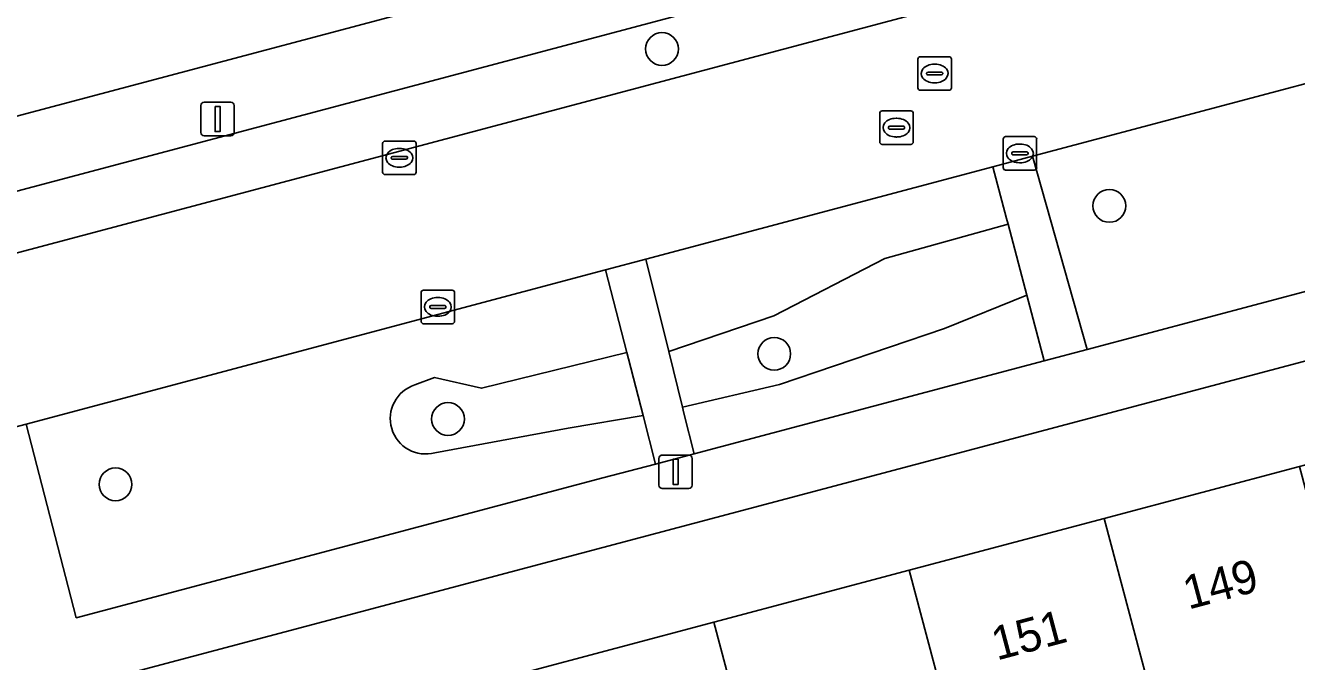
# Model space of a CAD drawing. Extents: x 162542 to 163147, y 380779 to 381521.
# Drawn here: x 162694.02 to 162731.96, y 381102.27 to 381121.27 of the extents above; entities that cross this region are included whole.
import ezdxf

# ---------------------------------------------------------------- set-up
doc = ezdxf.new("R2010")
doc.units = 0
for name, color, linetype in [('IMGEO_Boom', 7, 'Continuous'), ('IMGEO_Erf', 7, 'Continuous'), ('IMGEO_Groenvoorziening', 7, 'Continuous'), ('IMGEO_Kolk', 7, 'Continuous'), ('IMGEO_Lichtmast', 7, 'Continuous'), ('IMGEO_Pand', 7, 'Continuous'), ('IMGEO_Pand_nummerreeks', 7, 'Continuous'), ('IMGEO_Parkeervlak_open', 7, 'Continuous'), ('IMGEO_Rijbaan_lokaal_open', 7, 'Continuous'), ('IMGEO_Rioolput', 7, 'Continuous'), ('IMGEO_Voetpad_open', 7, 'Continuous')]:
    doc.layers.add(name, color=color, linetype=linetype)

msp = doc.modelspace()

# ---------------------------------------------------------------- linework, layer by layer
at = {"layer": 'IMGEO_Boom'}
for centre in [(162713.018, 381120.562), (162726.37, 381115.877), (162716.369, 381111.459), (162706.631, 381109.515), (162696.71, 381107.565)]:
    msp.add_circle(centre, 0.489, dxfattribs=at)
at = {"layer": 'IMGEO_Erf'}
for points in [[(162749.869, 381133.472), (162749.085, 381136.384), (162743.131, 381134.8), (162737.328, 381133.255), (162731.525, 381131.711), (162725.722, 381130.167), (162719.919, 381128.623), (162714.116, 381127.079), (162708.313, 381125.534), (162702.51, 381123.99), (162696.707, 381122.446), (162690.904, 381120.902), (162684.977, 381119.324), (162684.888, 381119.301), (162684.115, 381122.206), (162678.746, 381120.787), (162680.279, 381114.986), (162685.734, 381116.428)], [(162732.042, 381108.097), (162737.868, 381109.646), (162743.693, 381111.195), (162749.519, 381112.744), (162755.344, 381114.293), (162761.17, 381115.842), (162761.884, 381112.936), (162767.441, 381114.419), (162765.901, 381120.189), (162760.455, 381118.748), (162696.302, 381101.71), (162697.083, 381098.802), (162702.914, 381100.353), (162708.739, 381101.902), (162714.565, 381103.451), (162720.391, 381104.999), (162726.216, 381106.548)]]:
    msp.add_lwpolyline(points, close=True, dxfattribs=at)
at = {"layer": 'IMGEO_Groenvoorziening'}
for points in [[(162724.071, 381117.358), (162725.703, 381111.591), (162736.038, 381114.335), (162734.561, 381120.153)], [(162723.348, 381115.329), (162723.302, 381115.505), (162722.896, 381117.045), (162712.54, 381114.286), (162713.22, 381111.534), (162716.356, 381112.599), (162719.667, 381114.311)], [(162723.906, 381113.217), (162723.348, 381115.329), (162719.667, 381114.311), (162716.356, 381112.599), (162713.22, 381111.534), (162713.631, 381109.869), (162716.529, 381110.546), (162721.454, 381112.219)], [(162722.471, 381110.733), (162724.424, 381111.251), (162723.906, 381113.217), (162721.454, 381112.219), (162716.529, 381110.546), (162713.631, 381109.869), (162713.674, 381109.694), (162713.974, 381108.477)]]:
    msp.add_lwpolyline(points, close=True, dxfattribs=at)
for points in [[(162711.97, 381111.5), (162711.337, 381113.966), (162694.038, 381109.357), (162695.539, 381103.583), (162711.256, 381107.755), (162712.824, 381108.171), (162712.452, 381109.619), (162710.222, 381109.238), (162706.243, 381108.509)], [(162705.645, 381110.534), (162706.226, 381110.759), (162707.629, 381110.434), (162711.97, 381111.5)], [(162712.018, 381111.312), (162711.97, 381111.5), (162707.629, 381110.434), (162706.226, 381110.759), (162705.645, 381110.534)], [(162706.243, 381108.509), (162710.222, 381109.238), (162712.452, 381109.619), (162712.018, 381111.312)]]:
    msp.add_lwpolyline(points, dxfattribs=at)
msp.add_arc((162705.964, 381109.527), 1.056, 107.5972, 285.3075, dxfattribs=at)
msp.add_arc((162705.964, 381109.527), 1.056, 107.5972, 285.3075, dxfattribs=at)
at = {"layer": 'IMGEO_Kolk'}
for p, q in [((162723.274, 381117.945), (162724.126, 381117.945)), ((162704.679, 381116.887), (162704.679, 381117.739)), ((162704.754, 381117.813), (162705.606, 381117.813)), ((162705.167, 381117.593), (162705.192, 381117.593)), ((162705.68, 381117.739), (162705.68, 381116.887)), ((162723.199, 381117.019), (162723.199, 381117.871)), ((162723.687, 381117.725), (162723.712, 381117.725)), ((162724.2, 381117.871), (162724.2, 381117.019)), ((162704.938, 381117.307), (162704.938, 381117.319)), ((162705.376, 381117.27), (162704.978, 381117.27)), ((162704.981, 381117.356), (162705.379, 381117.356)), ((162705.422, 381117.319), (162705.422, 381117.307)), ((162723.458, 381117.439), (162723.458, 381117.451)), ((162723.896, 381117.402), (162723.498, 381117.402)), ((162723.501, 381117.488), (162723.899, 381117.488)), ((162723.71, 381117.165), (162723.685, 381117.165)), ((162723.942, 381117.451), (162723.942, 381117.439)), ((162705.606, 381116.813), (162704.754, 381116.813)), ((162705.19, 381117.033), (162705.165, 381117.033)), ((162724.126, 381116.945), (162723.274, 381116.945)), ((162705.827, 381112.435), (162705.827, 381113.287)), ((162705.902, 381113.361), (162706.754, 381113.361)), ((162706.315, 381113.141), (162706.34, 381113.141)), ((162706.828, 381113.287), (162706.828, 381112.435)), ((162706.086, 381112.855), (162706.086, 381112.867)), ((162706.524, 381112.818), (162706.126, 381112.818)), ((162706.129, 381112.904), (162706.527, 381112.904)), ((162706.57, 381112.867), (162706.57, 381112.855)), ((162706.754, 381112.361), (162705.902, 381112.361)), ((162706.338, 381112.581), (162706.313, 381112.581))]:
    msp.add_line(p, q, dxfattribs=at)
for points in [[(162723.274, 381117.945), (162724.126, 381117.945)], [(162704.679, 381116.887), (162704.679, 381117.739)], [(162704.754, 381117.813), (162705.606, 381117.813)], [(162705.68, 381117.739), (162705.68, 381116.887)], [(162723.199, 381117.019), (162723.199, 381117.871)], [(162724.2, 381117.871), (162724.2, 381117.019)], [(162705.606, 381116.813), (162704.754, 381116.813)], [(162724.126, 381116.945), (162723.274, 381116.945)], [(162705.827, 381112.435), (162705.827, 381113.287)], [(162705.902, 381113.361), (162706.754, 381113.361)], [(162706.828, 381113.287), (162706.828, 381112.435)], [(162706.754, 381112.361), (162705.902, 381112.361)]]:
    msp.add_lwpolyline(points, dxfattribs=at)
for centre, radius, start, end in [((162723.276, 381117.869), 0.0765, 91.552, 178.448), ((162723.276, 381117.869), 0.0765, 91.552, 178.448), ((162724.124, 381117.869), 0.0765, 1.552, 88.448), ((162724.124, 381117.869), 0.0765, 1.552, 88.448), ((162704.756, 381117.737), 0.0765, 91.552, 178.448), ((162704.756, 381117.737), 0.0765, 91.552, 178.448), ((162705.604, 381117.737), 0.0765, 1.552, 88.448), ((162705.604, 381117.737), 0.0765, 1.552, 88.448), ((162704.978, 381117.316), 0.0403, 85.8775, 175.7526), ((162704.975, 381117.306), 0.0366, 178.938, 274.7102), ((162705.379, 381117.313), 0.043, 264.8664, 352.4533), ((162705.383, 381117.318), 0.0386, 1.7309, 96.639), ((162723.498, 381117.448), 0.0403, 85.8775, 175.7526), ((162723.495, 381117.438), 0.0366, 178.938, 274.7102), ((162723.899, 381117.445), 0.043, 264.8664, 352.4533), ((162723.903, 381117.45), 0.0386, 1.7309, 96.639), ((162704.756, 381116.889), 0.0765, 181.552, 268.448), ((162704.756, 381116.889), 0.0765, 181.552, 268.448), ((162705.604, 381116.889), 0.0765, 271.552, 358.448), ((162705.604, 381116.889), 0.0765, 271.552, 358.448), ((162723.276, 381117.021), 0.0765, 181.552, 268.448), ((162723.276, 381117.021), 0.0765, 181.552, 268.448), ((162724.124, 381117.021), 0.0765, 271.552, 358.448), ((162724.124, 381117.021), 0.0765, 271.552, 358.448), ((162705.904, 381113.285), 0.0765, 91.552, 178.448), ((162705.904, 381113.285), 0.0765, 91.552, 178.448), ((162706.752, 381113.285), 0.0765, 1.552, 88.448), ((162706.752, 381113.285), 0.0765, 1.552, 88.448), ((162706.126, 381112.864), 0.0403, 85.8775, 175.7526), ((162706.123, 381112.854), 0.0366, 178.938, 274.7102), ((162706.527, 381112.861), 0.043, 264.8664, 352.4533), ((162706.531, 381112.866), 0.0386, 1.7309, 96.639), ((162705.904, 381112.437), 0.0765, 181.552, 268.448), ((162705.904, 381112.437), 0.0765, 181.552, 268.448), ((162706.752, 381112.437), 0.0765, 271.552, 358.448), ((162706.752, 381112.437), 0.0765, 271.552, 358.448)]:
    msp.add_arc(centre, radius, start, end, dxfattribs=at)
for centre, major_axis, ratio, start_param, end_param in [((162705.166, 381117.313), (-0.387, 0.002), 0.722429, 4.712389, 7.853982), ((162705.191, 381117.313), (-0.39, 0.002), 0.717154, 1.570796, 4.712389), ((162723.686, 381117.445), (-0.387, 0.002), 0.722429, 4.712389, 7.853982), ((162723.711, 381117.445), (-0.39, 0.002), 0.717154, 1.570796, 4.712389), ((162706.314, 381112.861), (-0.387, 0.002), 0.722429, 4.712389, 7.853982), ((162706.339, 381112.861), (-0.39, 0.002), 0.717154, 1.570796, 4.712389)]:
    msp.add_ellipse(centre, major_axis=major_axis, ratio=ratio, start_param=start_param, end_param=end_param, dxfattribs=at)
at = {"layer": 'IMGEO_Lichtmast'}
for p, q in [((162699.258, 381118.071), (162699.258, 381118.871)), ((162699.258, 381118.871), (162699.258, 381118.071)), ((162699.358, 381118.971), (162700.148, 381118.971)), ((162700.148, 381118.971), (162699.358, 381118.971)), ((162700.248, 381118.871), (162700.248, 381118.071)), ((162700.248, 381118.071), (162700.248, 381118.871)), ((162700.148, 381117.971), (162699.358, 381117.971)), ((162699.358, 381117.971), (162700.148, 381117.971)), ((162713.028, 381108.44), (162713.818, 381108.44)), ((162713.818, 381108.44), (162713.028, 381108.44)), ((162712.928, 381107.54), (162712.928, 381108.34)), ((162712.928, 381108.34), (162712.928, 381107.54)), ((162713.918, 381108.34), (162713.918, 381107.54)), ((162713.918, 381107.54), (162713.918, 381108.34)), ((162713.818, 381107.44), (162713.028, 381107.44)), ((162713.028, 381107.44), (162713.818, 381107.44))]:
    msp.add_line(p, q, dxfattribs=at)
for points in [[(162699.678, 381118.846), (162699.828, 381118.846), (162699.828, 381118.096), (162699.678, 381118.096), (162699.678, 381118.846)], [(162713.348, 381108.315), (162713.498, 381108.315), (162713.498, 381107.565), (162713.348, 381107.565), (162713.348, 381108.315)]]:
    msp.add_lwpolyline(points, dxfattribs=at)
for centre, start, end in [((162699.358, 381118.871), 90, 180), ((162699.358, 381118.871), 90, 180), ((162700.148, 381118.871), 0, 90), ((162700.148, 381118.871), 360, 90), ((162699.358, 381118.071), 180, 270), ((162699.358, 381118.071), 180, 270), ((162700.148, 381118.071), 270, 0), ((162700.148, 381118.071), 270, 0), ((162713.028, 381108.34), 90, 180), ((162713.028, 381108.34), 90, 180), ((162713.818, 381108.34), 0, 90), ((162713.818, 381108.34), 360, 90), ((162713.028, 381107.54), 180, 270), ((162713.028, 381107.54), 180, 270), ((162713.818, 381107.54), 270, 0), ((162713.818, 381107.54), 270, 0)]:
    msp.add_arc(centre, 0.1, start, end, dxfattribs=at)
at = {"layer": 'IMGEO_Pand'}
for points in [[(162732.042, 381108.097), (162726.216, 381106.548), (162728.785, 381096.887), (162734.611, 381098.436)], [(162726.216, 381106.548), (162720.391, 381104.999), (162722.959, 381095.339), (162728.785, 381096.887)], [(162714.565, 381103.451), (162717.134, 381093.79), (162722.959, 381095.339), (162720.391, 381104.999)], [(162708.739, 381101.902), (162711.308, 381092.241), (162717.134, 381093.79), (162714.565, 381103.451)]]:
    msp.add_lwpolyline(points, close=True, dxfattribs=at)
at = {"layer": 'IMGEO_Parkeervlak_open'}
msp.add_lwpolyline([(162750.234, 381131.33), (162666.499, 381109.073), (162666.934, 381107.34), (162774.201, 381135.871), (162796.063, 381141.696), (162882.877, 381164.808), (162901.876, 381169.92), (162904.167, 381170.544), (162903.648, 381172.331), (162882.303, 381166.521), (162850.91, 381158.201), (162843.113, 381156.134), (162825.633, 381151.487), (162819.826, 381149.913), (162790.747, 381142.166), (162781.519, 381139.707), (162755.957, 381132.897)], close=True, dxfattribs=at)
at = {"layer": 'IMGEO_Rijbaan_lokaal_open'}
for points in [[(162752.751, 381124.999), (162754.693, 381125.516), (162758.591, 381126.553), (162768.331, 381129.144), (162769.49, 381129.452), (162775.451, 381131.037), (162774.201, 381135.871), (162666.934, 381107.34), (162664.853, 381106.777)], [(162692.09, 381108.85), (162694.038, 381109.357), (162711.337, 381113.966), (162712.54, 381114.286), (162722.896, 381117.045), (162724.071, 381117.358), (162734.561, 381120.153), (162735.727, 381120.464), (162752.751, 381124.999)]]:
    msp.add_lwpolyline(points, dxfattribs=at)
at = {"layer": 'IMGEO_Rioolput'}
for p, q in [((162720.655, 381119.404), (162720.655, 381120.256)), ((162720.73, 381120.33), (162721.582, 381120.33)), ((162721.656, 381120.256), (162721.656, 381119.404)), ((162720.914, 381119.824), (162720.914, 381119.836)), ((162720.957, 381119.873), (162721.355, 381119.873)), ((162721.143, 381120.11), (162721.168, 381120.11)), ((162721.398, 381119.836), (162721.398, 381119.824)), ((162721.352, 381119.787), (162720.954, 381119.787)), ((162721.166, 381119.55), (162721.141, 381119.55)), ((162721.582, 381119.33), (162720.73, 381119.33)), ((162719.59, 381118.714), (162720.442, 381118.714)), ((162719.515, 381117.788), (162719.515, 381118.64)), ((162720.003, 381118.494), (162720.028, 381118.494)), ((162720.516, 381118.64), (162720.516, 381117.788)), ((162719.774, 381118.208), (162719.774, 381118.22)), ((162720.212, 381118.171), (162719.814, 381118.171)), ((162719.817, 381118.257), (162720.215, 381118.257)), ((162720.026, 381117.934), (162720.001, 381117.934)), ((162720.258, 381118.22), (162720.258, 381118.208)), ((162720.442, 381117.714), (162719.59, 381117.714))]:
    msp.add_line(p, q, dxfattribs=at)
for points in [[(162720.655, 381119.404), (162720.655, 381120.256)], [(162720.73, 381120.33), (162721.582, 381120.33)], [(162721.656, 381120.256), (162721.656, 381119.404)], [(162721.582, 381119.33), (162720.73, 381119.33)], [(162719.59, 381118.714), (162720.442, 381118.714)], [(162719.515, 381117.788), (162719.515, 381118.64)], [(162720.516, 381118.64), (162720.516, 381117.788)], [(162720.442, 381117.714), (162719.59, 381117.714)]]:
    msp.add_lwpolyline(points, dxfattribs=at)
for centre, radius, start, end in [((162720.732, 381120.254), 0.0765, 91.552, 178.448), ((162720.732, 381120.254), 0.0765, 91.552, 178.448), ((162721.58, 381120.254), 0.0765, 1.552, 88.448), ((162721.58, 381120.254), 0.0765, 1.552, 88.448), ((162720.954, 381119.833), 0.0403, 85.8775, 175.7526), ((162720.951, 381119.823), 0.0366, 178.938, 274.7102), ((162721.355, 381119.83), 0.043, 264.8664, 352.4533), ((162721.359, 381119.835), 0.0386, 1.7309, 96.639), ((162720.732, 381119.406), 0.0765, 181.552, 268.448), ((162720.732, 381119.406), 0.0765, 181.552, 268.448), ((162721.58, 381119.406), 0.0765, 271.552, 358.448), ((162721.58, 381119.406), 0.0765, 271.552, 358.448), ((162719.592, 381118.638), 0.0765, 91.552, 178.448), ((162719.592, 381118.638), 0.0765, 91.552, 178.448), ((162720.44, 381118.638), 0.0765, 1.552, 88.448), ((162720.44, 381118.638), 0.0765, 1.552, 88.448), ((162719.814, 381118.217), 0.0403, 85.8775, 175.7526), ((162719.811, 381118.207), 0.0366, 178.938, 274.7102), ((162720.215, 381118.214), 0.043, 264.8664, 352.4533), ((162720.219, 381118.219), 0.0386, 1.7309, 96.639), ((162719.592, 381117.79), 0.0765, 181.552, 268.448), ((162719.592, 381117.79), 0.0765, 181.552, 268.448), ((162720.44, 381117.79), 0.0765, 271.552, 358.448), ((162720.44, 381117.79), 0.0765, 271.552, 358.448)]:
    msp.add_arc(centre, radius, start, end, dxfattribs=at)
for centre, major_axis, ratio, start_param, end_param in [((162721.142, 381119.83), (-0.387, 0.002), 0.722429, 4.712389, 7.853982), ((162721.167, 381119.83), (-0.39, 0.002), 0.717154, 1.570796, 4.712389), ((162720.002, 381118.214), (-0.387, 0.002), 0.722429, 4.712389, 7.853982), ((162720.027, 381118.214), (-0.39, 0.002), 0.717154, 1.570796, 4.712389)]:
    msp.add_ellipse(centre, major_axis=major_axis, ratio=ratio, start_param=start_param, end_param=end_param, dxfattribs=at)
at = {"layer": 'IMGEO_Voetpad_open'}
for points in [[(162749.869, 381133.472), (162685.734, 381116.428)], [(162666.934, 381107.34), (162666.499, 381109.073), (162750.234, 381131.33)], [(162782.046, 381131.197), (162783.201, 381126.857), (162782.697, 381126.723), (162771.037, 381123.628), (162769.877, 381123.32), (162760.047, 381120.71), (162756.301, 381119.715), (162754.347, 381119.196), (162737.289, 381114.667), (162736.038, 381114.335), (162725.703, 381111.591), (162724.424, 381111.251), (162722.471, 381110.733), (162713.974, 381108.477), (162712.824, 381108.171), (162711.256, 381107.755), (162695.539, 381103.583), (162694.038, 381109.357), (162692.09, 381108.85)], [(162632.291, 381081.579), (162637.577, 381082.985), (162642.863, 381084.391), (162648.149, 381085.798), (162647.384, 381088.694), (162652.83, 381090.149), (162655.504, 381090.86), (162658.845, 381091.748), (162664.86, 381093.347), (162670.32, 381094.788), (162684.374, 381098.519), (162693.826, 381101.081), (162696.302, 381101.71), (162760.455, 381118.748)]]:
    msp.add_lwpolyline(points, dxfattribs=at)
for points in [[(162724.071, 381117.358), (162722.896, 381117.045), (162723.302, 381115.505), (162723.348, 381115.329), (162723.906, 381113.217), (162724.424, 381111.251), (162725.703, 381111.591)], [(162713.22, 381111.534), (162712.54, 381114.286), (162711.337, 381113.966), (162711.97, 381111.5), (162712.018, 381111.312), (162712.452, 381109.619), (162712.824, 381108.171), (162713.974, 381108.477), (162713.674, 381109.694), (162713.631, 381109.869)]]:
    msp.add_lwpolyline(points, close=True, dxfattribs=at)

# ---------------------------------------------------------------- texts
at = {"layer": 'IMGEO_Pand_nummerreeks'}
for s, p in [('149', (162728.728, 381103.822)), ('151', (162723.012, 381102.302))]:
    msp.add_text(s, height=1, rotation=14.8893, dxfattribs=at).set_placement(p)

doc.saveas('drawing.dxf')
